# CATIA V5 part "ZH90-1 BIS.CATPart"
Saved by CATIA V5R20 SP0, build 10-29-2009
Part number: ZH901BIS
Bounding box of the stored display mesh (mm): x 0 to 179, y -20 to 55, z -29.7 to 15
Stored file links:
  C:\Users\Utente\Desktop\IO LAVORO\3D X SITO CF\X SITO\PLASTICA\ZH90\ZH90-1 BIS.CATPart
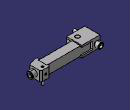
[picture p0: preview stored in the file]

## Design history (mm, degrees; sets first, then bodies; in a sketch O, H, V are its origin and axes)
Set1
  DatumSurface1 to DatumSurface16 "_ZH90/1 BIS_head"
  DatumSurface17 to DatumSurface34 "_ZH90/1 BIS_screw1"
  DatumSurface35 to DatumSurface55 "_ZH90/1 BIS_hand"
  DatumSurface56 to DatumSurface73 "_ZH90/1 BIS_screw2"
  DatumSurface74 to DatumSurface94 "_ZH90/1 BIS_he"
  DatumSurface95 to DatumSurface109 "_ZH90/1 BIS_screw3"
  DatumSurface110 to DatumSurface117 "_ZH90/1 BIS_stift1"
  DatumSurface118 to DatumSurface127 "_ZH90/1 BIS_stift2"
Body1 (main body)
